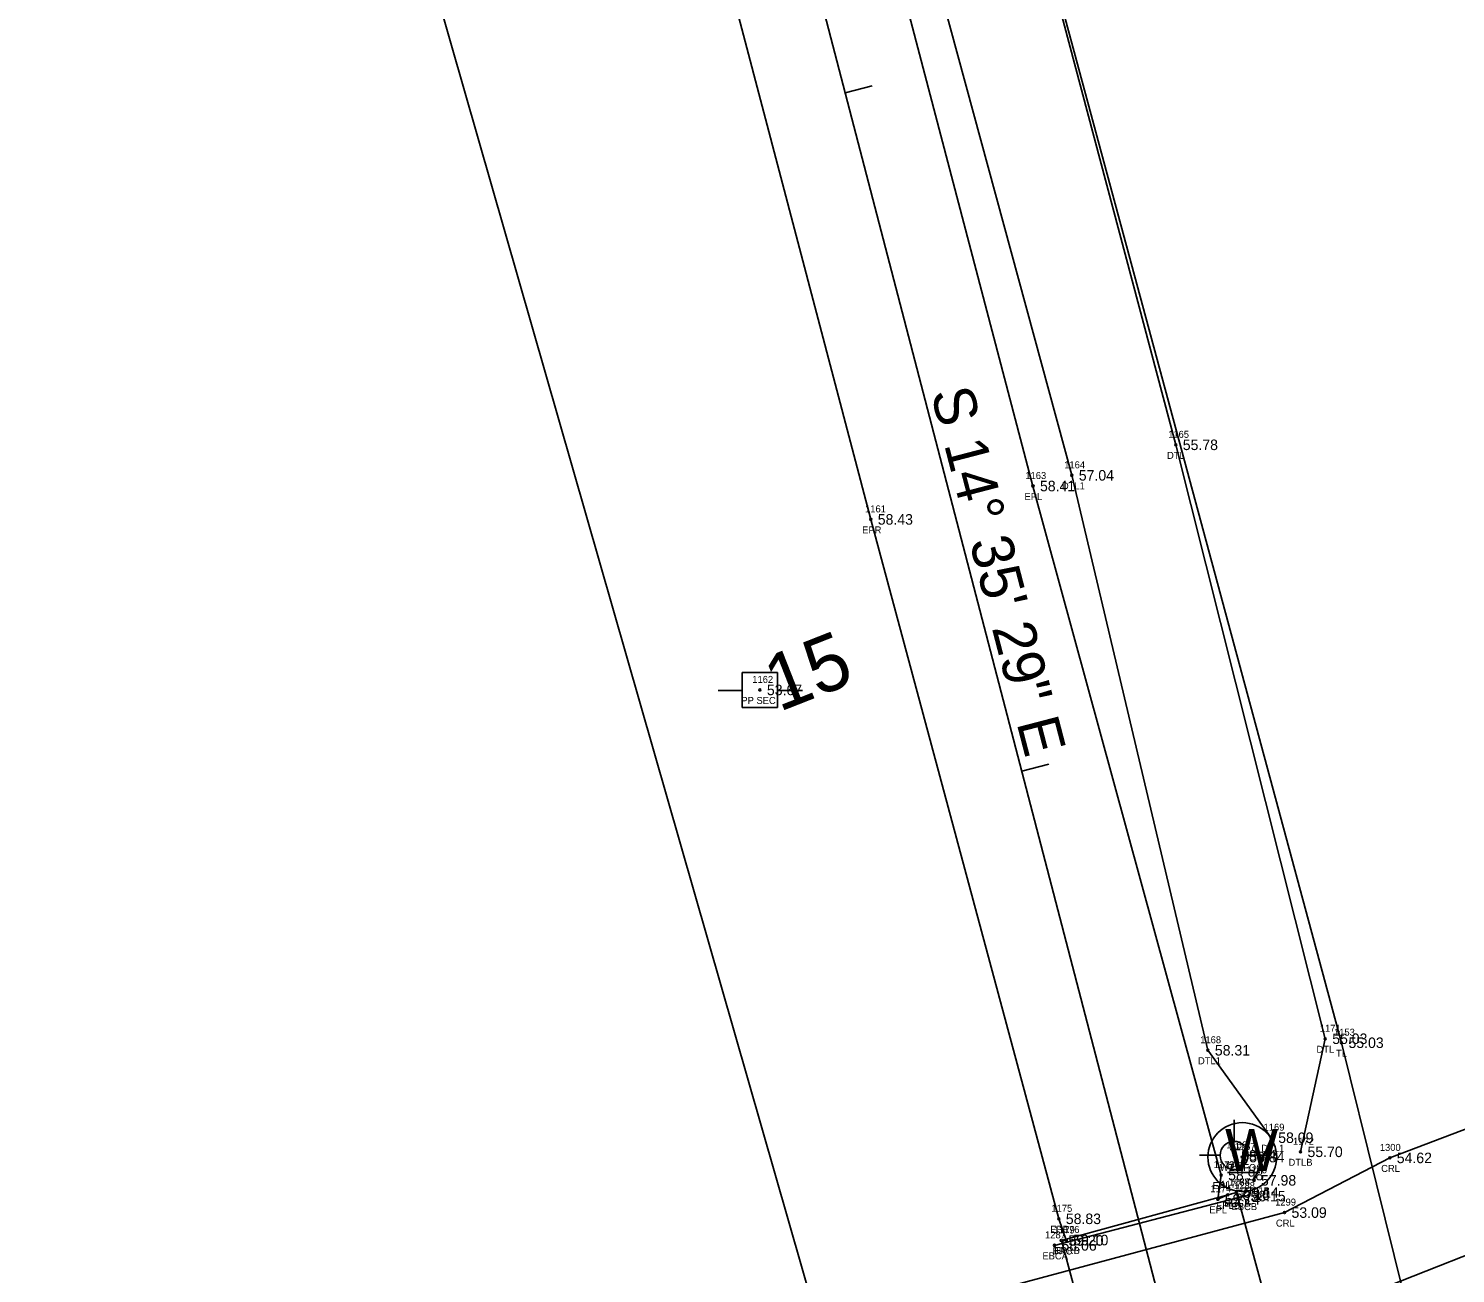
# Model space of a CAD drawing. Extents: x 2396531 to 2397633, y 770203 to 772837.
# Drawn here: x 2396890.9 to 2397094.6, y 771396.5 to 771574.1 of the extents above; entities that cross this region are included whole.
import ezdxf

# ---------------------------------------------------------------- set-up
doc = ezdxf.new("R2010")
doc.units = 0
for name, color, linetype in [('RD_EX_Bridge', 7, 'Continuous'), ('RD_EX_Bridge_txCode', 7, 'Continuous'), ('RD_EX_H2O', 7, 'Continuous'), ('RD_EX_H2O_txCode', 7, 'Continuous'), ('RD_EX_Road', 7, 'Continuous'), ('RD_EX_Road_txCode', 7, 'Continuous'), ('RD_EX_TX_Bridge_ELEV', 7, 'Continuous'), ('RD_EX_TX_H2O_ELEV', 7, 'Continuous'), ('RD_EX_TX_Road_ELEV', 7, 'Continuous'), ('RD_EX_TX_UT_ELEV', 7, 'Continuous'), ('RD_EX_TX_VEG_ELEV', 7, 'Continuous'), ('RD_EX_UT', 7, 'Continuous'), ('RD_EX_UT_txCode', 7, 'Continuous'), ('RD_EX_VEG', 7, 'Continuous'), ('RD_EX_VEG_txCode', 7, 'Continuous'), ('RD_HC_Cl', 7, 'Continuous'), ('RD_HC_Data', 7, 'Continuous'), ('RD_HC_Data_Tic', 7, 'Continuous'), ('RD_HC_Survey_ELEV', 7, 'Continuous'), ('RD_HC_TX_Sta50', 7, 'Continuous'), ('RD_SMD_Locator', 7, 'Continuous')]:
    doc.layers.add(name, color=color, linetype=linetype)

msp = doc.modelspace()

# ---------------------------------------------------------------- linework, layer by layer
at = {"layer": 'RD_EX_Bridge'}
msp.add_line((2397037.33, 771400.46), (2397064.3, 771407.49), dxfattribs=at)
msp.add_lwpolyline([(2397063.31, 771408), (2397038.31, 771401.16), (2397050, 771357.89), (2397075.04, 771364.66), (2397063.31, 771408)], dxfattribs=at)
at = {"layer": 'RD_EX_H2O'}
for points in [[(2397132.06, 771727.73), (2397069.65, 771707.99), (2397027.41, 771693.94), (2396997.29, 771683.71), (2397009.52, 771621.94), (2397039.8, 771510.33), (2397059.22, 771428.3), (2397068.26, 771415.82), (2397065.8, 771409.74)], [(2397133.83, 771721.66), (2397071.25, 771701.52), (2397031.62, 771688.97), (2397008.91, 771681.79), (2397013.82, 771672.05), (2397025.11, 771625.88), (2397054.64, 771514.68), (2397075.97, 771429.94), (2397072.44, 771413.81)], [(2397026.41, 771393.39), (2397070.16, 771405.14), (2397085.18, 771412.94), (2397115.64, 771424.52), (2397174.69, 771450.34), (2397230.25, 771466.48), (2397283.24, 771491.48), (2397342.91, 771519.42), (2397408.89, 771536.24), (2397447.46, 771546.47), (2397469.5, 771549.6), (2397497.19, 771541.27), (2397541.1, 771500.79)]]:
    msp.add_lwpolyline(points, dxfattribs=at)
at = {"layer": 'RD_EX_Road'}
for points in [[(2396680.92, 772617.84), (2396715.6, 772525.73), (2396750.68, 772430.62), (2396786.3, 772332.21), (2396811.38, 772263.31), (2396839.69, 772181.74), (2396863.75, 772109.83), (2396883.63, 772046.56), (2396889.54, 772027.11), (2396896.25, 772004.37), (2396904.34, 771978.33), (2396908.24, 771964.89), (2396921.74, 771919.68), (2396927.03, 771902.11), (2396950.2, 771821.74), (2396970.47, 771750.68), (2396978.33, 771721.29), (2396990.58, 771675.04), (2397004.94, 771620.49), (2397034.26, 771508.8), (2397061.11, 771410.49), (2397060.64, 771407.04), (2397062.07, 771407.67)], [(2396658.78, 772611.07), (2396693.37, 772516.9), (2396729.65, 772418.78), (2396760.7, 772333.11), (2396788.58, 772254.87), (2396814.65, 772181.57), (2396841.1, 772100.86), (2396861.19, 772037.76), (2396886.09, 771955.71), (2396907.15, 771884.49), (2396928.56, 771811.72), (2396947.65, 771744.09), (2396985.17, 771602.64), (2397011.11, 771504.04), (2397037.95, 771404.25), (2397039, 771401.22)]]:
    msp.add_lwpolyline(points, dxfattribs=at)
at = {"layer": 'RD_EX_UT'}
for p, q in [((2396997.78, 771482.22), (2396992.78, 771482.22)), ((2396992.78, 771482.22), (2396992.78, 771477.22)), ((2396997.78, 771477.22), (2396997.78, 771482.22)), ((2396989.35, 771479.65), (2396992.82, 771479.65)), ((2396997.71, 771479.65), (2397001.35, 771479.65)), ((2396992.78, 771477.22), (2396997.78, 771477.22)), ((2397062.96, 771418.37), (2397062.96, 771415.3)), ((2397058.03, 771413.32), (2397060.96, 771413.32)), ((2397064.96, 771413.32), (2397068.03, 771413.32)), ((2397062.01, 771410.85), (2397066.63, 771410.85))]:
    msp.add_line(p, q, dxfattribs=at)
for centre, radius in [((2397064.13, 771413.06), 4.91), ((2397062.96, 771413.3), 2)]:
    msp.add_circle(centre, radius, dxfattribs=at)
at = {"layer": 'RD_EX_VEG'}
for points in [[(2396666.35, 772324.52), (2396746.5, 772348.13), (2396878.43, 771953.6), (2396907.83, 771806.94), (2396910.04, 771736.08), (2396945.43, 771592.11), (2397049.51, 771229.15), (2396980.16, 771221.67)], [(2397137.17, 771710.16), (2397010.6, 771680.28), (2397078.29, 771429.37), (2397127.02, 771232.69), (2397127.02, 771232.69), (2397166.52, 771123.83), (2397178.02, 771098.29), (2397254.06, 771102.5)]]:
    msp.add_lwpolyline(points, dxfattribs=at)
at = {"layer": 'RD_HC_Cl'}
for p, q in [((2396987, 771643.49), (2397064.7, 771345.02)), ((2396577.63, 771195.09), (2397449.32, 771538.02))]:
    msp.add_line(p, q, dxfattribs=at)
at = {"layer": 'RD_HC_Data_Tic'}
for p, q in [((2397007.46, 771564.91), (2397011.33, 771565.92)), ((2397032.65, 771468.14), (2397036.52, 771469.14))]:
    msp.add_line(p, q, dxfattribs=at)
at = {"layer": 'RD_SMD_Locator'}
for centre in [(2397054.64, 771514.68), (2397039.8, 771510.33), (2397034.26, 771508.8), (2397011.11, 771504.04), (2396995.29, 771479.71), (2397059.22, 771428.3), (2397075.97, 771429.94), (2397078.29, 771429.37), (2397068.26, 771415.82), (2397062.96, 771413.3), (2397064.13, 771413.06), (2397072.44, 771413.81), (2397085.18, 771412.94), (2397061.11, 771410.49), (2397063.31, 771408), (2397063.31, 771408), (2397065.8, 771409.74), (2397060.64, 771407.04), (2397062.07, 771407.67), (2397064.3, 771407.49), (2397037.95, 771404.25), (2397070.16, 771405.14), (2397037.33, 771400.46), (2397038.31, 771401.16), (2397039, 771401.22)]:
    msp.add_circle(centre, 0.15, dxfattribs=at)

# ---------------------------------------------------------------- texts
at = {"layer": 'RD_EX_Bridge_txCode'}
for s, p in [('1178', (2397062.24, 771409)), ('1184', (2397062.24, 771409)), ('1288', (2397062.96, 771408.49)), ('BRCA', (2397061.57, 771406)), ('BRCB', (2397061.58, 771406)), ('EBCB', (2397062.6, 771405.49)), ('1287', (2397035.98, 771401.46)), ('1179', (2397037.24, 771402.16)), ('BRC', (2397037.05, 771399.16)), ('EBCA', (2397035.61, 771398.46))]:
    msp.add_text(s, height=1, dxfattribs=at).set_placement(p)
at = {"layer": 'RD_EX_H2O_txCode'}
for s, p in [('1165', (2397053.55, 771515.68)), ('1164', (2397038.72, 771511.33)), ('DTL', (2397053.39, 771512.68)), ('DTL1', (2397038.39, 771508.33)), ('1171', (2397075.19, 771430.94)), ('1168', (2397058.13, 771429.3)), ('DTL', (2397074.72, 771427.94)), ('DTL1', (2397057.81, 771426.3)), ('1169', (2397067.17, 771416.82)), ('DTL1', (2397066.85, 771413.82)), ('1172', (2397071.38, 771414.81)), ('1300', (2397083.76, 771413.94)), ('DTLB', (2397070.73, 771411.81)), ('1170', (2397064.69, 771410.74)), ('CRL', (2397083.95, 771410.94)), ('DTL1B', (2397063.92, 771407.74)), ('1299', (2397068.82, 771406.14)), ('CRL', (2397068.93, 771403.14))]:
    msp.add_text(s, height=1, dxfattribs=at).set_placement(p)
at = {"layer": 'RD_EX_Road_txCode'}
for s, p in [('1163', (2397033.17, 771509.8)), ('1161', (2397010.3, 771505.04)), ('EPL', (2397033.05, 771506.8)), ('EPR', (2397009.88, 771502.04)), ('1173', (2397060.05, 771411.49)), ('1174', (2397059.58, 771408.04)), ('EPL', (2397059.91, 771408.49)), ('1177', (2397061.01, 771408.67)), ('1175', (2397036.89, 771405.25)), ('EPL', (2397059.43, 771405.04)), ('EPLB', (2397060.39, 771405.67)), ('EPR', (2397036.72, 771402.25)), ('1176', (2397037.92, 771402.22)), ('EPRB', (2397037.3, 771399.22))]:
    msp.add_text(s, height=1, dxfattribs=at).set_placement(p)
at = {"layer": 'RD_EX_TX_Bridge_ELEV'}
for s, p in [('59.14', (2397064.31, 771407.25)), ('59.14', (2397064.31, 771407.25)), ('58.15', (2397065.3, 771406.74)), ('58.06', (2397038.33, 771399.71)), ('59.20', (2397039.31, 771400.41))]:
    msp.add_text(s, height=1.5, dxfattribs=at).set_placement(p)
at = {"layer": 'RD_EX_TX_H2O_ELEV'}
for s, p in [('55.78', (2397055.64, 771513.93)), ('57.04', (2397040.8, 771509.58)), ('55.03', (2397076.97, 771429.19)), ('58.31', (2397060.22, 771427.55)), ('58.09', (2397069.26, 771415.07)), ('55.70', (2397073.44, 771413.06)), ('54.62', (2397086.18, 771412.19)), ('57.98', (2397066.8, 771408.99)), ('53.09', (2397071.16, 771404.39))]:
    msp.add_text(s, height=1.5, dxfattribs=at).set_placement(p)
at = {"layer": 'RD_EX_TX_Road_ELEV'}
for s, p in [('58.41', (2397035.26, 771508.05)), ('58.43', (2397012.11, 771503.29)), ('58.98', (2397062.11, 771409.74)), ('59.10', (2397063.07, 771406.92)), ('59.14', (2397061.64, 771406.29)), ('58.83', (2397038.95, 771403.5)), ('59.10', (2397040, 771400.47))]:
    msp.add_text(s, height=1.5, dxfattribs=at).set_placement(p)
at = {"layer": 'RD_EX_TX_UT_ELEV'}
for s, p in [('58.44', (2397063.96, 771412.55)), ('58.84', (2397065.13, 771412.31))]:
    msp.add_text(s, height=1.5, dxfattribs=at).set_placement(p)
at = {"layer": 'RD_EX_TX_VEG_ELEV'}
msp.add_text('55.03', height=1.5, dxfattribs=at).set_placement((2397079.29, 771428.62))
at = {"layer": 'RD_EX_UT'}
for s, height, p in [('W', 6, (2397061.67, 771411.06)), ('T', 2, (2397062.3, 771412.25))]:
    msp.add_text(s, height=height, dxfattribs=at).set_placement(p)
at = {"layer": 'RD_EX_UT_txCode'}
for s, p in [('1162', (2396994.2, 771480.71)), ('PP SEC', (2396992.64, 771477.71)), ('1166', (2397061.85, 771414.3)), ('1167', (2397063.05, 771414.06)), ('TPP', (2397061.7, 771411.3)), ('WTS FOC', (2397060.92, 771411.06))]:
    msp.add_text(s, height=1, dxfattribs=at).set_placement(p)
at = {"layer": 'RD_EX_VEG_txCode'}
for s, p in [('1153', (2397077.22, 771430.37)), ('TL', (2397077.51, 771427.37))]:
    msp.add_text(s, height=1, dxfattribs=at).set_placement(p)
at = {"layer": 'RD_HC_Data'}
msp.add_text('S 14%%d 35\' 29" E', height=6, rotation=284.5913, dxfattribs=at).set_placement((2397019.64, 771522.1))
at = {"layer": 'RD_HC_Survey_ELEV'}
msp.add_text('53.67', height=1.5, dxfattribs=at).set_placement((2396996.29, 771478.96))
at = {"layer": 'RD_HC_TX_Sta50'}
msp.add_text('15', height=8, rotation=21.4751, dxfattribs=at).set_placement((2396998.02, 771476.53))

doc.saveas('drawing.dxf')
